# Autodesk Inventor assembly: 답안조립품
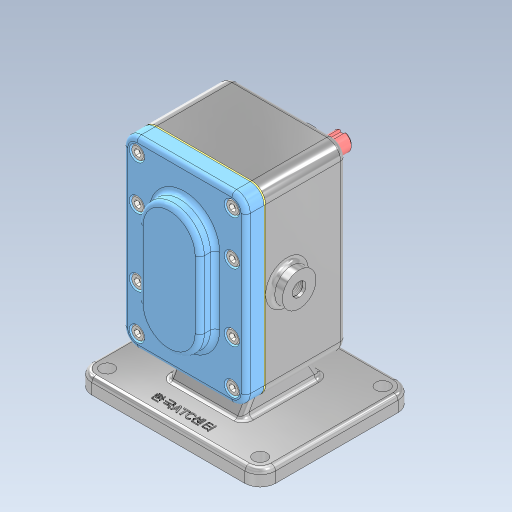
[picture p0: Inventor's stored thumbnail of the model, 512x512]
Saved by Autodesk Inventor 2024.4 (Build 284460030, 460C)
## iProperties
Created: 2026-10
Part Number: 답안조립품
Document SubType Name: Assembly
Designer: user
Author: user
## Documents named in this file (11)
- C:\Users\user\Desktop\761003V1006\답안조립품.iam
- C:\Users\user\Desktop\761003V1006\본체.ipt
- C:\Users\user\Desktop\761003V1006\6각 구멍붙이 볼트 M5x16.ipt
- C:\Users\user\Desktop\761003V1006\개스킷.ipt
- C:\Users\user\Desktop\761003V1006\구동 축.ipt
- C:\Users\user\Desktop\761003V1006\베어링 부시.ipt
- C:\Users\user\Desktop\761003V1006\스퍼 기어.ipt
- C:\Users\user\Desktop\761003V1006\오일 실 16 28 7.ipt
- C:\Users\user\Desktop\761003V1006\종동 축.ipt
- C:\Users\user\Desktop\761003V1006\커버.ipt
- C:\Users\user\Desktop\761003V1006\평행 키 6x6x18.ipt
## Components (10 placed, 3 different names)
1. 6각 구멍붙이 볼트 M5x16:1 — 각도:2, 각도:7, 각도:8
2. 개스킷:1
3. 구동 축:1 — 각도:1
4. 6각 구멍붙이 볼트 M5x16:2 — 각도:8, 각도:9
5. 6각 구멍붙이 볼트 M5x16:3 — 각도:9, 각도:10
6. 6각 구멍붙이 볼트 M5x16:4 — 각도:10
7. 6각 구멍붙이 볼트 M5x16:5 — 각도:3, 각도:4
8. 6각 구멍붙이 볼트 M5x16:6 — 각도:4, 각도:5
9. 6각 구멍붙이 볼트 M5x16:7 — 각도:6
10. 6각 구멍붙이 볼트 M5x16:8 — 각도:5, 각도:6
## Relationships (10: Angle 10)
- 각도:1 [Angle]: 구동 축:1
- 각도:2 [Angle]: 6각 구멍붙이 볼트 M5x16:1
- 각도:3 [Angle]: 6각 구멍붙이 볼트 M5x16:5
- 각도:4 [Angle]: 6각 구멍붙이 볼트 M5x16:5 ↔ 6각 구멍붙이 볼트 M5x16:6
- 각도:5 [Angle]: 6각 구멍붙이 볼트 M5x16:6 ↔ 6각 구멍붙이 볼트 M5x16:8
- 각도:6 [Angle]: 6각 구멍붙이 볼트 M5x16:7 ↔ 6각 구멍붙이 볼트 M5x16:8
- 각도:7 [Angle]: 6각 구멍붙이 볼트 M5x16:1
- 각도:8 [Angle]: 6각 구멍붙이 볼트 M5x16:1 ↔ 6각 구멍붙이 볼트 M5x16:2
- 각도:9 [Angle]: 6각 구멍붙이 볼트 M5x16:2 ↔ 6각 구멍붙이 볼트 M5x16:3
- 각도:10 [Angle]: 6각 구멍붙이 볼트 M5x16:3 ↔ 6각 구멍붙이 볼트 M5x16:4
